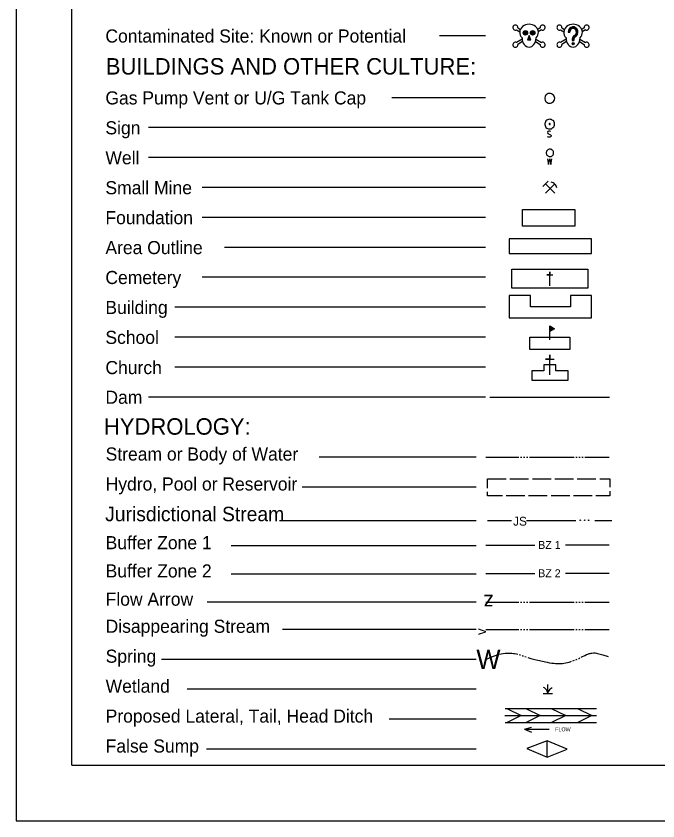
# Model space of a CAD drawing. Extents: x 0 to 3, y 0 to 1.83.
# Drawn here: x 0 to 0.722, y 0 to 0.904 of the extents above; entities that cross this region are included whole.
import ezdxf

# ---------------------------------------------------------------- set-up
doc = ezdxf.new("R2010")
doc.units = 0
for name, color, linetype in [('Sheet_Plan', 7, 'Continuous'), ('Sheet_Symbology', 7, 'Continuous'), ('z - Construction', 7, 'Continuous')]:
    doc.layers.add(name, color=color, linetype=linetype)

msp = doc.modelspace()

# ---------------------------------------------------------------- linework, layer by layer
at = {"layer": 'Sheet_Plan'}
for q in [(0.06249, 1.77083), (2.77079, 0.0625)]:
    msp.add_line((0.0625, 0.0625), q, dxfattribs=at)
at = {"layer": 'Sheet_Symbology'}
for p, q in [((0.56276, 0.88884), (0.56628, 0.88662)), ((0.56415, 0.89106), (0.56701, 0.88926)), ((0.58925, 0.89106), (0.5864, 0.88926)), ((0.59065, 0.88884), (0.58712, 0.88662)), ((0.61224, 0.88884), (0.61577, 0.88662)), ((0.61364, 0.89106), (0.61649, 0.88926)), ((0.62079, 0.88613), (0.62245, 0.88613)), ((0.63874, 0.89106), (0.63588, 0.88926)), ((0.64013, 0.88884), (0.63661, 0.88662)), ((0.5278, 0.88205), (0.47594, 0.88205)), ((0.56891, 0.87827), (0.56276, 0.87441)), ((0.5767, 0.88162), (0.5767, 0.88162)), ((0.58449, 0.87827), (0.59065, 0.87441)), ((0.6184, 0.87827), (0.61224, 0.87441)), ((0.62535, 0.87825), (0.62535, 0.87679)), ((0.62559, 0.87825), (0.62559, 0.87679)), ((0.62583, 0.87825), (0.62583, 0.87679)), ((0.62607, 0.87825), (0.62607, 0.87679)), ((0.62619, 0.88248), (0.62619, 0.88248)), ((0.62631, 0.87825), (0.62631, 0.87679)), ((0.62655, 0.87825), (0.62655, 0.87679)), ((0.62678, 0.87825), (0.62678, 0.87679)), ((0.62702, 0.87825), (0.62702, 0.87679)), ((0.63398, 0.87827), (0.64013, 0.87441)), ((0.56951, 0.87555), (0.56415, 0.87218)), ((0.5839, 0.87555), (0.58925, 0.87218)), ((0.61899, 0.87555), (0.61364, 0.87218)), ((0.62535, 0.87679), (0.62702, 0.87679)), ((0.63338, 0.87555), (0.63874, 0.87218)), ((0.5278, 0.81253), (0.42255, 0.81253)), ((0.5278, 0.77889), (0.14873, 0.77889)), ((0.5278, 0.74526), (0.14873, 0.74526)), ((0.59525, 0.7156), (0.59221, 0.71256)), ((0.59525, 0.70513), (0.60572, 0.7156)), ((0.5278, 0.71163), (0.20927, 0.71163)), ((0.60049, 0.71037), (0.59989, 0.71096)), ((0.60049, 0.71037), (0.60572, 0.70513)), ((0.56948, 0.68681), (0.62833, 0.68681)), ((0.56948, 0.668), (0.56948, 0.68681)), ((0.62833, 0.68681), (0.62833, 0.668)), ((0.5278, 0.678), (0.20927, 0.678)), ((0.62833, 0.668), (0.56948, 0.668)), ((0.64696, 0.65412), (0.55447, 0.65412)), ((0.55447, 0.65412), (0.55447, 0.63731)), ((0.64696, 0.63731), (0.64696, 0.65412)), ((0.5278, 0.64437), (0.23441, 0.64437)), ((0.55447, 0.63731), (0.64696, 0.63731)), ((0.55725, 0.61986), (0.64277, 0.61986)), ((0.55725, 0.59834), (0.55725, 0.61986)), ((0.64277, 0.61986), (0.64277, 0.59834)), ((0.5278, 0.61074), (0.20927, 0.61074)), ((0.64277, 0.59834), (0.55725, 0.59834)), ((0.57829, 0.59029), (0.55447, 0.59029)), ((0.55447, 0.59029), (0.55447, 0.56506)), ((0.57829, 0.57767), (0.57829, 0.59029)), ((0.64696, 0.59029), (0.62314, 0.59029)), ((0.62314, 0.59029), (0.62314, 0.57767)), ((0.64696, 0.56506), (0.64696, 0.59029)), ((0.5278, 0.57711), (0.17852, 0.57711)), ((0.62314, 0.57767), (0.57829, 0.57767)), ((0.55447, 0.56506), (0.64696, 0.56506)), ((0.5278, 0.54348), (0.17852, 0.54348)), ((0.57747, 0.54348), (0.62241, 0.54348)), ((0.57747, 0.52952), (0.57747, 0.54348)), ((0.62241, 0.54348), (0.62241, 0.52952)), ((0.62241, 0.52952), (0.57747, 0.52952)), ((0.5278, 0.50984), (0.17852, 0.50984)), ((0.60698, 0.51235), (0.59336, 0.51235)), ((0.59336, 0.51235), (0.59336, 0.50556)), ((0.60698, 0.50556), (0.60698, 0.51235)), ((0.59336, 0.50556), (0.57974, 0.50556)), ((0.57974, 0.50556), (0.57974, 0.49532)), ((0.6206, 0.50556), (0.60698, 0.50556)), ((0.6206, 0.49532), (0.6206, 0.50556)), ((0.57974, 0.49532), (0.6206, 0.49532)), ((0.5278, 0.47621), (0.14873, 0.47621)), ((0.53263, 0.47621), (0.66716, 0.47621)), ((0.51727, 0.40862), (0.3407, 0.40862)), ((0.52822, 0.40862), (0.56526, 0.40862)), ((0.56694, 0.40862), (0.56862, 0.40862)), ((0.5703, 0.40862), (0.57198, 0.40862)), ((0.57366, 0.40862), (0.57534, 0.40862)), ((0.57703, 0.40862), (0.62747, 0.40862)), ((0.62915, 0.40862), (0.63084, 0.40862)), ((0.63252, 0.40862), (0.6342, 0.40862)), ((0.63588, 0.40862), (0.63756, 0.40862)), ((0.63924, 0.40862), (0.66695, 0.40862)), ((0.53001, 0.38436), (0.55103, 0.38436)), ((0.53001, 0.37377), (0.53001, 0.38436)), ((0.55523, 0.38436), (0.57625, 0.38436)), ((0.58045, 0.38436), (0.60147, 0.38436)), ((0.60568, 0.38436), (0.6267, 0.38436)), ((0.6309, 0.38436), (0.65192, 0.38436)), ((0.51727, 0.37499), (0.32155, 0.37499)), ((0.572, 0.36532), (0.55098, 0.36532)), ((0.59723, 0.36532), (0.57621, 0.36532)), ((0.62245, 0.36532), (0.60143, 0.36532)), ((0.64767, 0.36532), (0.62665, 0.36532)), ((0.51727, 0.33699), (0.29597, 0.33699)), ((0.51727, 0.30905), (0.24191, 0.30905)), ((0.52822, 0.30978), (0.58336, 0.30978)), ((0.66695, 0.30978), (0.61767, 0.30978)), ((0.51727, 0.27732), (0.24191, 0.27732)), ((0.52822, 0.27787), (0.58336, 0.27787)), ((0.66695, 0.27787), (0.61767, 0.27787)), ((0.51727, 0.24559), (0.21486, 0.24559)), ((0.52822, 0.24559), (0.56526, 0.24559)), ((0.56694, 0.24559), (0.56862, 0.24559)), ((0.5703, 0.24559), (0.57198, 0.24559)), ((0.57366, 0.24559), (0.57534, 0.24559)), ((0.57703, 0.24559), (0.62747, 0.24559)), ((0.62915, 0.24559), (0.63084, 0.24559)), ((0.63252, 0.24559), (0.6342, 0.24559)), ((0.63588, 0.24559), (0.63756, 0.24559)), ((0.63924, 0.24559), (0.66695, 0.24559)), ((0.51727, 0.21512), (0.29948, 0.21512)), ((0.52822, 0.21512), (0.56526, 0.21512)), ((0.56694, 0.21512), (0.56862, 0.21512)), ((0.5703, 0.21512), (0.57198, 0.21512)), ((0.57366, 0.21512), (0.57534, 0.21512)), ((0.57703, 0.21512), (0.62747, 0.21512)), ((0.62915, 0.21512), (0.63084, 0.21512)), ((0.63252, 0.21512), (0.6342, 0.21512)), ((0.63588, 0.21512), (0.63756, 0.21512)), ((0.63924, 0.21512), (0.66695, 0.21512)), ((0.51727, 0.18149), (0.16334, 0.18149)), ((0.57196, 0.18477), (0.57356, 0.18422)), ((0.62924, 0.18109), (0.63077, 0.18174)), ((0.62611, 0.17985), (0.62766, 0.18048)), ((0.51727, 0.14786), (0.19237, 0.14786)), ((0.59777, 0.1433), (0.59777, 0.15318)), ((0.59245, 0.1433), (0.60317, 0.1433)), ((0.5496, 0.11835), (0.65263, 0.11835)), ((0.55004, 0.12642), (0.65263, 0.12642)), ((0.55155, 0.12642), (0.56801, 0.11835)), ((0.56801, 0.11835), (0.55201, 0.11053)), ((0.57293, 0.12642), (0.58939, 0.11835)), ((0.58939, 0.11835), (0.57345, 0.11053)), ((0.60143, 0.12642), (0.61795, 0.11835)), ((0.61795, 0.11835), (0.60202, 0.11053)), ((0.63126, 0.12642), (0.6474, 0.11835)), ((0.6474, 0.11835), (0.6317, 0.11053)), ((0.51727, 0.11423), (0.41944, 0.11423)), ((0.55004, 0.11053), (0.65263, 0.11053)), ((0.57148, 0.10296), (0.57955, 0.10523)), ((0.57148, 0.10296), (0.59948, 0.10296)), ((0.57148, 0.10296), (0.57955, 0.09968)), ((0.59723, 0.09003), (0.5744, 0.08116)), ((0.59723, 0.07145), (0.59723, 0.09003)), ((0.61961, 0.08074), (0.59723, 0.09003)), ((0.51727, 0.0806), (0.21412, 0.0806)), ((0.5744, 0.08116), (0.59723, 0.07145)), ((0.59723, 0.07145), (0.61961, 0.08074))]:
    msp.add_line(p, q, dxfattribs=at)
for points in [[(0.5767, 0.88248), (0.57486, 0.87744), (0.57855, 0.87744)], [(0.5767, 0.88162), (0.57528, 0.87773), (0.57813, 0.87773)], [(0.5767, 0.88076), (0.5757, 0.87803), (0.5777, 0.87803)], [(0.5767, 0.87991), (0.57612, 0.87832), (0.57728, 0.87832)], [(0.5767, 0.87905), (0.57654, 0.87862), (0.57686, 0.87862)]]:
    msp.add_lwpolyline(points, close=True, dxfattribs=at)
for points in [[(0.60554, 0.81181), (0.60523, 0.81315), (0.60494, 0.81434), (0.6042, 0.81539), (0.60315, 0.81628), (0.60211, 0.81688), (0.60092, 0.81733), (0.59957, 0.81733), (0.59823, 0.81717), (0.59704, 0.81658), (0.596, 0.81583), (0.59526, 0.81494), (0.59466, 0.81375), (0.59436, 0.81241), (0.59436, 0.81122), (0.59466, 0.80988), (0.59526, 0.80868), (0.596, 0.80779), (0.59704, 0.80705), (0.59823, 0.80645), (0.59957, 0.8063), (0.60092, 0.8063), (0.60211, 0.80675), (0.60315, 0.80735), (0.6042, 0.80824), (0.60494, 0.80928), (0.60523, 0.81047), (0.60554, 0.81181)], [(0.60538, 0.7828), (0.60527, 0.78389), (0.60494, 0.78499), (0.60439, 0.78597), (0.60363, 0.78673), (0.60276, 0.78739), (0.60177, 0.78794), (0.60079, 0.78815), (0.59959, 0.78826), (0.5985, 0.78804), (0.59751, 0.78772), (0.59653, 0.78717), (0.59576, 0.78641), (0.59511, 0.78542), (0.59467, 0.78444), (0.59445, 0.78335), (0.59445, 0.78226), (0.59467, 0.78116), (0.59511, 0.78018), (0.59576, 0.77919), (0.59653, 0.77843), (0.59751, 0.77788), (0.5985, 0.77756), (0.59959, 0.77734), (0.60079, 0.77745), (0.60177, 0.77767), (0.60276, 0.77821), (0.60363, 0.77887), (0.60439, 0.77963), (0.60494, 0.78062), (0.60527, 0.78171), (0.60538, 0.7828)], [(0.60013, 0.78345), (0.59981, 0.78345), (0.59948, 0.78324), (0.59926, 0.78291), (0.59937, 0.78258), (0.59959, 0.78226), (0.59991, 0.78214), (0.60024, 0.78226), (0.60046, 0.78247), (0.60057, 0.78291), (0.60046, 0.78324), (0.60013, 0.78345)], [(0.6012, 0.77438), (0.60014, 0.77486), (0.59892, 0.77486), (0.59781, 0.77438), (0.59733, 0.77354), (0.59733, 0.77322), (0.59786, 0.77242), (0.60093, 0.77083), (0.60146, 0.77009), (0.60141, 0.76946), (0.60093, 0.76861), (0.60003, 0.76813), (0.59876, 0.76813), (0.59818, 0.76834), (0.59733, 0.76893)], [(0.60437, 0.75049), (0.60424, 0.75122), (0.6041, 0.75195), (0.60377, 0.75261), (0.60331, 0.7532), (0.60278, 0.75374), (0.60218, 0.75413), (0.60145, 0.7544), (0.60073, 0.7546), (0.6, 0.7546), (0.59927, 0.75453), (0.59854, 0.75427), (0.59795, 0.75393), (0.59735, 0.75347), (0.59682, 0.75294), (0.59649, 0.75228), (0.59623, 0.75162), (0.59609, 0.75089), (0.59609, 0.75009), (0.59623, 0.74937), (0.59649, 0.7487), (0.59682, 0.74804), (0.59735, 0.74751), (0.59795, 0.74705), (0.59854, 0.74672), (0.59927, 0.74645), (0.6, 0.74639), (0.60073, 0.74639), (0.60145, 0.74658), (0.60218, 0.74685), (0.60278, 0.74725), (0.60331, 0.74778), (0.60377, 0.74837), (0.6041, 0.74903), (0.60424, 0.74976), (0.60437, 0.75049)], [(0.5975, 0.744), (0.59856, 0.73728), (0.59993, 0.744), (0.60131, 0.73728), (0.60248, 0.744)], [(0.60049, 0.71037), (0.59525, 0.7156), (0.59821, 0.71855)], [(0.60783, 0.71129), (0.60758, 0.71248), (0.60715, 0.71357), (0.60656, 0.71459), (0.6058, 0.71543), (0.60496, 0.71628), (0.60395, 0.71687), (0.60285, 0.71737), (0.60175, 0.71763)], [(0.60004, 0.60124), (0.60004, 0.617), (0.60004, 0.61365), (0.59669, 0.61365), (0.60339, 0.61365)], [(0.6, 0.54034), (0.6, 0.55611), (0.60527, 0.553), (0.6, 0.5499), (0.60031, 0.5504), (0.60031, 0.55567), (0.60465, 0.55294), (0.60062, 0.55059), (0.60068, 0.55518), (0.60416, 0.55294), (0.60099, 0.55114), (0.60099, 0.55462), (0.6036, 0.55294), (0.60136, 0.5517), (0.60136, 0.55406), (0.60304, 0.553), (0.60168, 0.5522), (0.60168, 0.5535), (0.60254, 0.553), (0.60198, 0.55269), (0.60192, 0.55307), (0.60211, 0.553)], [(0.60017, 0.501), (0.60017, 0.5237), (0.60017, 0.51887), (0.59534, 0.51887), (0.60499, 0.51887)], [(0.65612, 0.38436), (0.6676, 0.38436), (0.6676, 0.37482)], [(0.54678, 0.36532), (0.53001, 0.36532), (0.53001, 0.36957)], [(0.6676, 0.37062), (0.6676, 0.36532), (0.65188, 0.36532)], [(0.53001, 0.33732), (0.55692, 0.33732)], [(0.5738, 0.33732), (0.59738, 0.33732)], [(0.59738, 0.33732), (0.62933, 0.33732)], [(0.65051, 0.33732), (0.66971, 0.33732)], [(0.52824, 0.18149), (0.53301, 0.18349), (0.5378, 0.18551), (0.539, 0.18597), (0.54112, 0.1867), (0.54276, 0.18714), (0.54522, 0.18771), (0.5477, 0.18815), (0.54978, 0.18841), (0.55163, 0.18855), (0.55325, 0.1886), (0.55468, 0.1886), (0.55718, 0.18845), (0.55905, 0.18826), (0.56044, 0.18805), (0.56252, 0.18765), (0.56395, 0.18731)], [(0.56559, 0.18687), (0.56637, 0.18664), (0.56719, 0.18639)], [(0.56879, 0.18586), (0.56948, 0.18563), (0.57038, 0.18532)], [(0.57516, 0.18368), (0.57644, 0.18324), (0.57879, 0.18254), (0.58331, 0.18134), (0.58672, 0.18048), (0.59182, 0.1793), (0.59697, 0.17823), (0.59983, 0.17773), (0.60235, 0.17735), (0.60458, 0.1771), (0.60654, 0.17693), (0.60824, 0.17685), (0.60975, 0.1768), (0.61236, 0.17685), (0.61431, 0.17697), (0.61579, 0.17714), (0.61795, 0.17745), (0.6201, 0.17792), (0.62171, 0.17836), (0.62312, 0.17878), (0.62453, 0.17928)], [(0.63233, 0.18239), (0.63266, 0.18254), (0.63386, 0.18309)], [(0.63538, 0.18384), (0.63618, 0.18424), (0.63948, 0.18597), (0.64116, 0.18679), (0.6429, 0.1875), (0.64423, 0.18794), (0.6454, 0.18824), (0.64645, 0.18845), (0.64738, 0.1886), (0.64902, 0.1887), (0.65024, 0.1887), (0.65114, 0.18864), (0.65249, 0.18845), (0.65381, 0.18815), (0.65978, 0.18651), (0.66573, 0.18485)], [(0.59777, 0.1433), (0.59752, 0.14448), (0.59718, 0.14566), (0.59659, 0.14676), (0.59583, 0.14778), (0.59499, 0.1487), (0.59397, 0.14938), (0.59288, 0.14997)], [(0.59777, 0.1433), (0.59828, 0.14457), (0.59887, 0.14583), (0.59963, 0.14701), (0.60056, 0.14803), (0.60157, 0.14896), (0.60267, 0.1498)]]:
    msp.add_lwpolyline(points, dxfattribs=at)
for centre, radius in [((0.57265, 0.88534), 0.0025), ((0.57265, 0.88534), 0.0022), ((0.57265, 0.88534), 0.00191), ((0.57265, 0.88534), 0.00161), ((0.57265, 0.88534), 0.00132), ((0.57265, 0.88534), 0.00102), ((0.58076, 0.88534), 0.0025), ((0.58076, 0.88534), 0.0022), ((0.58076, 0.88534), 0.00191), ((0.58076, 0.88534), 0.00161), ((0.58076, 0.88534), 0.00132), ((0.58076, 0.88534), 0.00102), ((0.57265, 0.88534), 0.00073), ((0.57265, 0.88534), 0.000435), ((0.57265, 0.88534), 0.000141), ((0.58076, 0.88534), 0.00073), ((0.58076, 0.88534), 0.000435), ((0.58076, 0.88534), 0.000141), ((0.62625, 0.87316), 0.00119), ((0.62625, 0.87316), 0.000927), ((0.62625, 0.87316), 0.000657), ((0.62625, 0.87316), 0.000392), ((0.62625, 0.87316), 0.000127)]:
    msp.add_circle(centre, radius, dxfattribs=at)
for centre, start, end in [((0.56137, 0.89126), 355.89762, 299.80617), ((0.59203, 0.89126), 240.19383, 184.10238), ((0.61086, 0.89126), 355.89762, 299.80617), ((0.64152, 0.89126), 240.19383, 184.10238), ((0.56137, 0.87199), 60.19383, 4.10238), ((0.59203, 0.87199), 175.89762, 119.80617), ((0.61086, 0.87199), 60.19383, 4.10238), ((0.64152, 0.87199), 175.89762, 119.80617)]:
    msp.add_arc(centre, 0.00279, start, end, dxfattribs=at)
for centre, major_axis, ratio, start_param, end_param in [((0.5767, 0.88578), (0.01046, 0), 0.885014, 5.564242, 10.143721), ((0.62619, 0.88578), (0.01046, 0), 0.885014, 5.564242, 10.143721), ((0.62619, 0.88613), (0, 0.006), 0.9, 3.567618, 7.853982), ((0.62619, 0.88613), (0, 0.00574), 0.9, 3.567618, 7.853982), ((0.62619, 0.88613), (0, 0.00547), 0.9, 3.567618, 7.853982), ((0.62619, 0.88613), (0, 0.00521), 0.9, 3.567618, 7.853982), ((0.62619, 0.88613), (0, 0.00494), 0.9, 3.567618, 7.853982), ((0.62619, 0.88613), (0, 0.00468), 0.9, 3.567618, 7.853982), ((0.62619, 0.88613), (0, 0.00441), 0.9, 3.567618, 7.853982), ((0.62619, 0.88613), (0, 0.00415), 0.9, 3.567618, 7.853982), ((0.5767, 0.87979), (0, -0.01046), 0.752542, 4.722735, 7.843636), ((0.62619, 0.87979), (0, -0.01046), 0.752542, 4.722735, 7.843636), ((0.62941, 0.87825), (0, 0.0045), 0.9, 0.426026, 1.570796), ((0.62941, 0.87825), (0, 0.00424), 0.9, 0.426026, 1.570796), ((0.62941, 0.87825), (0, 0.00397), 0.9, 0.426026, 1.570796), ((0.62941, 0.87825), (0, 0.00371), 0.9, 0.426026, 1.570796), ((0.62941, 0.87825), (0, 0.00344), 0.9, 0.426026, 1.570796), ((0.62941, 0.87825), (0, 0.00318), 0.9, 0.426026, 1.570796), ((0.62941, 0.87825), (0, 0.00291), 0.9, 0.426026, 1.570796), ((0.62941, 0.87825), (0, 0.00265), 0.9, 0.426026, 1.570796)]:
    msp.add_ellipse(centre, major_axis=major_axis, ratio=ratio, start_param=start_param, end_param=end_param, dxfattribs=at)
for centre in [(0.63427, 0.33779), (0.63924, 0.33779), (0.64359, 0.33779)]:
    msp.add_ellipse(centre, major_axis=(0, 0.000331), ratio=0.938496, dxfattribs=at)
at = {"layer": 'z - Construction'}
for p, q in [((0, 1.83333), (0, 0)), ((0, 0), (2.83333, 0))]:
    msp.add_line(p, q, dxfattribs=at)

# ---------------------------------------------------------------- texts
at = {"layer": 'Sheet_Symbology'}
for s, height, p in [('Contaminated Site: Known or Potential', 0.0147137, (0.10041, 0.87444)), ('BUILDINGS AND OTHER CULTURE:', 0.0184972, (0.10087, 0.83851)), ('Gas Pump Vent or U/G Tank Cap', 0.0147137, (0.10041, 0.80492)), ('Sign', 0.014714, (0.10043, 0.77131)), ('Well', 0.014714, (0.10043, 0.73768)), ('Small Mine', 0.014714, (0.10043, 0.70402)), ('Foundation', 0.014714, (0.10043, 0.67039)), ('Area Outline', 0.0147137, (0.10043, 0.63676)), ('Cemetery', 0.014714, (0.10041, 0.60315)), ('Building', 0.014714, (0.10043, 0.56952)), ('School', 0.014714, (0.10041, 0.53589)), ('Church', 0.014714, (0.10045, 0.50194)), ('Dam', 0.014714, (0.10043, 0.46863)), ('HYDROLOGY:', 0.018497, (0.09877, 0.43389)), ('Stream or Body of Water', 0.0147137, (0.10068, 0.40482)), ('Hydro, Pool or Reservoir', 0.0147137, (0.10068, 0.37119)), ('Jurisdictional Stream', 0.0162204, (0.10012, 0.33666)), ('JS', 0.00993, (0.55879, 0.33173)), ('Buffer Zone 1', 0.0147137, (0.10068, 0.30525)), ('BZ 1', 0.008937, (0.58698, 0.30556)), ('Buffer Zone 2', 0.0147137, (0.10068, 0.27352)), ('BZ 2', 0.008937, (0.58698, 0.27378)), ('Flow Arrow', 0.014714, (0.10068, 0.24178)), ('Disappearing Stream', 0.0147137, (0.10068, 0.21132)), ('Spring', 0.014714, (0.10068, 0.17769)), ('W', 0.02144, (0.51752, 0.17077)), ('Wetland', 0.014714, (0.10068, 0.14405)), ('Proposed Lateral, Tail, Head Ditch', 0.0147137, (0.10068, 0.11042)), ('FLOW', 0.00436, (0.6061, 0.10069)), ('False Sump', 0.014714, (0.10068, 0.07679))]:
    msp.add_text(s, height=height, dxfattribs=at).set_placement(p)
for s, height, rotation, p in [('z', 0.01682, 180.00002, (0.53665, 0.254)), ('v', 0.0111, 89.75915, (0.52822, 0.20884))]:
    msp.add_text(s, height=height, rotation=rotation, dxfattribs=at).set_placement(p)

doc.saveas('drawing.dxf')
